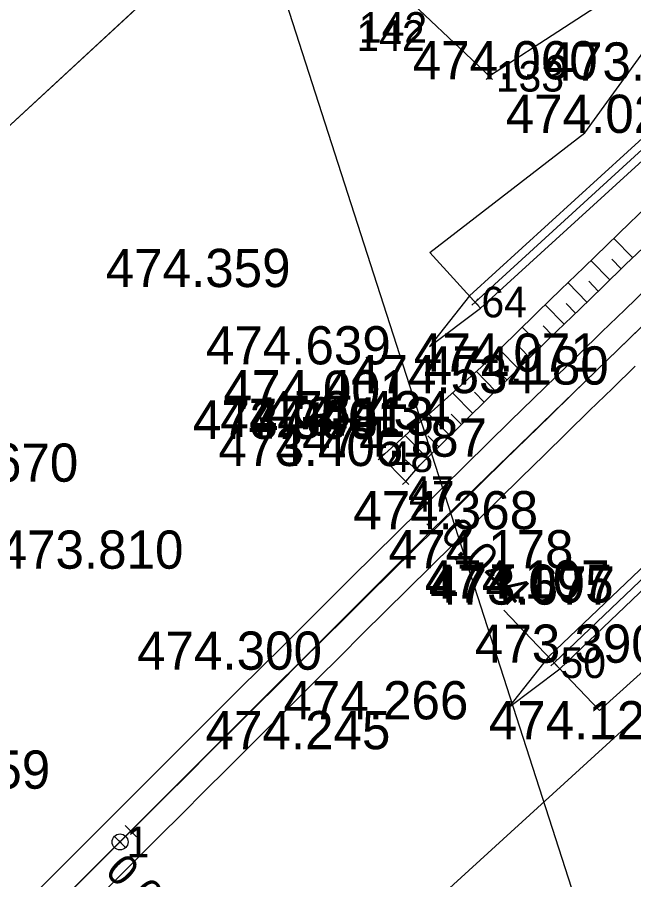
# Model space of a CAD drawing. Extents: x -758836 to -757729, y -1175316 to -1174366.
# Drawn here: x -758436.44 to -758417.1, y -1174871.85 to -1174844.78 of the extents above; entities that cross this region are included whole.
import ezdxf

# ---------------------------------------------------------------- set-up
doc = ezdxf.new("R2010")
doc.units = 0
for name, color, linetype in [('_NOR-body-Nolč', 7, 'Continuous'), ('_NOR-body-stávající osa', 7, 'Continuous'), ('_NOR-návrh tenká', 7, 'Continuous'), ('_NOR-osa', 7, 'Continuous'), ('_NOR-popis', 7, 'Continuous'), ('_NOR-posuny', 7, 'Continuous'), ('_NOR-svahy', 7, 'Continuous'), ('_NOR-vytyčení', 7, 'Continuous'), ('_vytyčený bod', 7, 'Continuous'), ('G_Obvod stavby', 7, 'Continuous'), ('Hranice parcel', 7, 'Continuous'), ('KOS_kabely SSZT', 7, 'Continuous'), ('Vrstva 1', 7, 'Continuous'), ('Vrstva 61', 7, 'Continuous')]:
    doc.layers.add(name, color=color, linetype=linetype)

# ---------------------------------------------------------------- blocks, each defined once
blk = doc.blocks.new('POINT_DISPLAY')
for p, q in [((-0.175, -0.175), (0.175, 0.175)), ((-0.175, 0.175), (0.175, -0.175))]:
    blk.add_line(p, q)

msp = doc.modelspace()

# ---------------------------------------------------------------- linework, layer by layer
at = {"layer": '_NOR-návrh tenká'}
for p, q in [((-758422.251, -1174853.527), (-758412.913, -1174844.999)), ((-758422.076, -1174853.719), (-758412.725, -1174845.179)), ((-758421.9, -1174853.911), (-758412.538, -1174845.36)), ((-758419.775, -1174864.854), (-758406.31, -1174852.017)), ((-758423.492, -1174852.168), (-758421.9, -1174853.911)), ((-758419.596, -1174865.042), (-758406.131, -1174852.205)), ((-758419.417, -1174865.23), (-758405.951, -1174852.393)), ((-758422.251, -1174853.527), (-758423.506, -1174855.117)), ((-758423.506, -1174855.117), (-758421.9, -1174853.911)), ((-758418.166, -1174866.541), (-758408.177, -1174857.467)), ((-758425.015, -1174858.575), (-758424.251, -1174859.35)), ((-758421.172, -1174863.389), (-758418.166, -1174866.541)), ((-758419.775, -1174864.854), (-758421.024, -1174866.442)), ((-758421.024, -1174866.442), (-758419.417, -1174865.23))]:
    msp.add_line(p, q, dxfattribs=at)
for points in [[(-758423.492, -1174852.168), (-758418.628, -1174848.411), (-758415.351, -1174843.865), (-758413.475, -1174842.592)], [(-758425.015, -1174858.575), (-758421.886, -1174855.769), (-758421.539, -1174855.429), (-758420.821, -1174854.729), (-758420.102, -1174854.029), (-758419.383, -1174853.33), (-758418.662, -1174852.631), (-758417.941, -1174851.934), (-758417.218, -1174851.237), (-758416.494, -1174850.542), (-758415.769, -1174849.847), (-758415.043, -1174849.154), (-758414.315, -1174848.461), (-758413.586, -1174847.77), (-758412.856, -1174847.08), (-758412.472, -1174846.718), (-758410.523, -1174846.054)], [(-758424.251, -1174859.35), (-758423.804, -1174858.844), (-758423.09, -1174858.141), (-758422.376, -1174857.439), (-758421.661, -1174856.738), (-758420.944, -1174856.037), (-758420.227, -1174855.337), (-758419.51, -1174854.638), (-758418.791, -1174853.94), (-758418.071, -1174853.242), (-758417.35, -1174852.545), (-758416.628, -1174851.85), (-758415.905, -1174851.155), (-758415.181, -1174850.461), (-758414.456, -1174849.769), (-758413.73, -1174849.077), (-758413.002, -1174848.387), (-758412.273, -1174847.698), (-758411.543, -1174847.01), (-758410.811, -1174846.324), (-758410.523, -1174846.054)], [(-758444.324, -1174880.698), (-758433.744, -1174870.135), (-758433.036, -1174869.428), (-758432.329, -1174868.722), (-758431.621, -1174868.015), (-758430.913, -1174867.309), (-758430.204, -1174866.602), (-758429.496, -1174865.896), (-758428.787, -1174865.19), (-758428.078, -1174864.485), (-758427.369, -1174863.78), (-758426.659, -1174863.075), (-758425.949, -1174862.37), (-758425.238, -1174861.666), (-758424.527, -1174860.962), (-758423.815, -1174860.259), (-758423.102, -1174859.556), (-758422.389, -1174858.854), (-758421.675, -1174858.153), (-758420.961, -1174857.452), (-758420.245, -1174856.752), (-758419.529, -1174856.053), (-758418.812, -1174855.355), (-758418.094, -1174854.657), (-758417.376, -1174853.961), (-758416.656, -1174853.265)], [(-758443.264, -1174881.76), (-758432.684, -1174871.196), (-758431.976, -1174870.49), (-758431.269, -1174869.783), (-758430.561, -1174869.077), (-758429.853, -1174868.371), (-758429.145, -1174867.665), (-758428.437, -1174866.959), (-758427.729, -1174866.254), (-758427.02, -1174865.548), (-758426.311, -1174864.844), (-758425.602, -1174864.139), (-758424.893, -1174863.435), (-758424.183, -1174862.732), (-758423.472, -1174862.029), (-758422.761, -1174861.327), (-758422.049, -1174860.625), (-758421.337, -1174859.924), (-758420.625, -1174859.223), (-758419.911, -1174858.524), (-758419.197, -1174857.825), (-758418.482, -1174857.127), (-758417.766, -1174856.43), (-758417.05, -1174855.734)]]:
    msp.add_lwpolyline(points, dxfattribs=at)
at = {"layer": '_NOR-osa'}
msp.add_line((-758443.794, -1174881.229), (-758433.214, -1174870.666), dxfattribs=at)
msp.add_lwpolyline([(-758433.214, -1174870.666), (-758432.506, -1174869.959), (-758431.799, -1174869.252), (-758431.091, -1174868.546), (-758430.383, -1174867.84), (-758429.675, -1174867.134), (-758428.967, -1174866.428), (-758428.258, -1174865.722), (-758427.549, -1174865.017), (-758426.84, -1174864.312), (-758426.131, -1174863.607), (-758425.421, -1174862.903), (-758424.71, -1174862.199), (-758423.999, -1174861.496), (-758423.288, -1174860.793), (-758422.576, -1174860.091), (-758421.863, -1174859.389), (-758421.15, -1174858.688), (-758420.436, -1174857.988), (-758419.721, -1174857.289), (-758419.006, -1174856.59), (-758418.289, -1174855.892), (-758417.572, -1174855.196), (-758416.854, -1174854.5)], dxfattribs=at)
msp.add_circle((-758433.214, -1174870.666), 0.25, dxfattribs=at)
at = {"layer": '_NOR-popis'}
msp.add_lwpolyline([(-758421.971, -1174894), (-758412.929, -1174891.088), (-758431.963, -1174831.996)], dxfattribs=at)
at = {"layer": '_NOR-svahy'}
for points in [[(-758417.129, -1174852.332), (-758417.719, -1174851.72)], [(-758417.848, -1174853.027), (-758418.439, -1174852.416)], [(-758417.489, -1174852.679), (-758417.784, -1174852.374)], [(-758418.567, -1174853.723), (-758419.158, -1174853.112)], [(-758418.208, -1174853.375), (-758418.504, -1174853.069)], [(-758419.284, -1174854.419), (-758419.877, -1174853.81)], [(-758418.926, -1174854.071), (-758419.222, -1174853.766)], [(-758419.643, -1174854.768), (-758419.939, -1174854.463)], [(-758420.001, -1174855.117), (-758420.594, -1174854.508)], [(-758420.717, -1174855.815), (-758421.311, -1174855.207)], [(-758420.359, -1174855.466), (-758420.656, -1174855.162)], [(-758421.432, -1174856.514), (-758422.032, -1174855.9)], [(-758421.074, -1174856.164), (-758421.372, -1174855.861)], [(-758422.146, -1174857.214), (-758422.778, -1174856.569)], [(-758421.789, -1174856.864), (-758422.097, -1174856.55)], [(-758422.859, -1174857.915), (-758423.524, -1174857.238)], [(-758422.503, -1174857.564), (-758422.827, -1174857.234)], [(-758423.572, -1174858.616), (-758424.27, -1174857.907)], [(-758423.216, -1174858.265), (-758423.557, -1174857.919)], [(-758423.92, -1174858.975), (-758424.308, -1174858.632)]]:
    msp.add_lwpolyline(points, dxfattribs=at)
at = {"layer": '_vytyčený bod'}
for p, q in [((-758421.625, -1174846.633), (-758421.725, -1174846.533)), ((-758421.625, -1174846.633), (-758421.725, -1174846.733)), ((-758421.625, -1174846.633), (-758421.525, -1174846.533)), ((-758421.625, -1174846.633), (-758421.525, -1174846.733)), ((-758422.076, -1174853.719), (-758422.176, -1174853.619)), ((-758422.076, -1174853.719), (-758421.976, -1174853.619)), ((-758422.076, -1174853.719), (-758422.176, -1174853.819)), ((-758422.076, -1174853.719), (-758421.976, -1174853.819)), ((-758425.015, -1174858.575), (-758425.115, -1174858.475)), ((-758425.015, -1174858.575), (-758424.915, -1174858.475)), ((-758425.015, -1174858.575), (-758425.115, -1174858.675)), ((-758425.015, -1174858.575), (-758424.915, -1174858.675)), ((-758424.251, -1174859.35), (-758424.351, -1174859.25)), ((-758424.251, -1174859.35), (-758424.351, -1174859.45)), ((-758424.251, -1174859.35), (-758424.151, -1174859.25)), ((-758424.251, -1174859.35), (-758424.151, -1174859.45)), ((-758419.596, -1174865.042), (-758419.696, -1174864.942)), ((-758419.596, -1174865.042), (-758419.696, -1174865.142)), ((-758419.596, -1174865.042), (-758419.496, -1174864.942)), ((-758419.596, -1174865.042), (-758419.496, -1174865.142)), ((-758433.214, -1174870.665), (-758433.314, -1174870.565)), ((-758433.214, -1174870.665), (-758433.314, -1174870.765)), ((-758433.214, -1174870.665), (-758433.114, -1174870.565)), ((-758433.214, -1174870.665), (-758433.114, -1174870.765))]:
    msp.add_line(p, q, dxfattribs=at)
at = {"layer": 'G_Obvod stavby'}
for points in [[(-758424.368, -1174835.441), (-758423.81, -1174836.28), (-758457.56, -1174867.46)], [(-758457.56, -1174867.46), (-758444.33, -1174881.69), (-758438.77, -1174887.67), (-758435.375, -1174884.045), (-758431.98, -1174880.42), (-758414.84, -1174864.78), (-758400.066, -1174851.383)]]:
    msp.add_lwpolyline(points, dxfattribs=at)
at = {"layer": 'Hranice parcel'}
msp.add_line((-758457.56, -1174867.46), (-758423.81, -1174836.28), dxfattribs=at)
msp.add_lwpolyline([(-758398.4, -1174849.12), (-758399.71, -1174851.06), (-758414.84, -1174864.78), (-758431.98, -1174880.42)], dxfattribs=at)
at = {"layer": 'KOS_kabely SSZT'}
msp.add_lwpolyline([(-758393.377, -1174840.127), (-758394.523, -1174839.636), (-758402.059, -1174830.861), (-758402.489, -1174830.243), (-758402.873, -1174830.574), (-758402.896, -1174831.429), (-758411.837, -1174839.758), (-758412.685, -1174838.202), (-758411.837, -1174839.758), (-758414.56, -1174842.041), (-758415.093, -1174841.478), (-758414.56, -1174842.041), (-758421.625, -1174846.632), (-758424.748, -1174843.672)], dxfattribs=at)
at = {"layer": 'Vrstva 1'}
msp.add_lwpolyline([(-758443.817, -1174881.252), (-758441.673, -1174879.1), (-758423.412, -1174860.854), (-758412.446, -1174850.23), (-758405.322, -1174843.614), (-758399.028, -1174837.996), (-758392.64, -1174832.554), (-758380.106, -1174822.693), (-758371.773, -1174816.721), (-758363.37, -1174811.125), (-758354.46, -1174805.649), (-758345.526, -1174800.592), (-758336.614, -1174795.909), (-758327.338, -1174791.462), (-758317.813, -1174787.314), (-758307.666, -1174783.315), (-758298.059, -1174779.921), (-758285.017, -1174775.914), (-758275.047, -1174773.289)], dxfattribs=at)

# ---------------------------------------------------------------- block references
at = {"layer": '_NOR-body-Nolč'}
msp.add_blockref('POINT_DISPLAY', (-758432.875, -1174870.327), dxfattribs=at)
at = {"layer": '_NOR-body-stávající osa'}
msp.add_blockref('POINT_DISPLAY', (-758423.412, -1174860.854), dxfattribs=at)
at = {"layer": '_NOR-vytyčení'}
msp.add_blockref('POINT_DISPLAY', (-758433.214, -1174870.666), dxfattribs=at)

# ---------------------------------------------------------------- texts
at = {"layer": '_NOR-body-Nolč'}
msp.add_text('0,000  (číslo bodu 66 - projekt p. Nolč)', height=0.95992, rotation=314.9548, dxfattribs=at).set_placement((-758433.723, -1174871.632))
at = {"layer": '_NOR-posuny'}
msp.add_text('0,044', height=0.9599, rotation=314.648, dxfattribs=at).set_placement((-758423.206, -1174861.063))
at = {"layer": '_vytyčený bod'}
for s, height, p in [('142', 0.9599, (-758425.72, -1174845.58)), ('142', 0.9596, (-758425.798, -1174845.835)), ('133', 0.9599, (-758421.425, -1174847.113)), ('133', 0.9596, (-758421.425, -1174847.113)), ('64', 0.9599, (-758421.876, -1174854.199)), ('64', 0.9596, (-758421.876, -1174854.199)), ('48', 0.9599, (-758424.815, -1174859.055)), ('48', 0.9596, (-758424.815, -1174859.055)), ('47', 0.9599, (-758424.174, -1174860.146)), ('47', 0.9596, (-758424.147, -1174860.298)), ('50', 0.9599, (-758419.396, -1174865.522)), ('50', 0.9596, (-758419.396, -1174865.522)), ('1', 0.96, (-758433.014, -1174871.145)), ('1', 0.96, (-758433.014, -1174871.145))]:
    msp.add_text(s, height=height, dxfattribs=at).set_placement(p)
at = {"layer": 'Vrstva 61'}
for s, p in [('474.060', (-758424.03, -1174846.73)), ('473.382', (-758419.863, -1174846.769)), ('474.028', (-758421.113, -1174848.411)), ('474.359', (-758433.664, -1174853.25)), ('474.639', (-758430.52, -1174855.677)), ('474.071', (-758423.995, -1174855.907)), ('474.180', (-758423.681, -1174856.311)), ('474.534', (-758425.966, -1174856.58)), ('474.401', (-758429.96, -1174857.056)), ('474.001', (-758429.973, -1174857.075)), ('473.434', (-758428.648, -1174857.714)), ('473.999', (-758430.931, -1174858.017)), ('474.398', (-758430.925, -1174858.004)), ('474.401', (-758430.069, -1174857.955)), ('474.413', (-758429.164, -1174857.911)), ('473.413', (-758429.162, -1174857.907)), ('474.187', (-758427.5, -1174858.575)), ('473.406', (-758430.127, -1174858.867)), ('474.406', (-758430.126, -1174858.868)), ('474.670', (-758440.325, -1174859.36)), ('474.368', (-758425.897, -1174860.854)), ('473.810', (-758437.025, -1174862.09)), ('474.178', (-758424.789, -1174862.079)), ('474.107', (-758423.653, -1174863.025)), ('474.095', (-758423.529, -1174863.158)), ('473.677', (-758423.484, -1174863.218)), ('473.390', (-758422.081, -1174865.042)), ('474.300', (-758432.679, -1174865.261)), ('474.266', (-758428.086, -1174866.818)), ('474.127', (-758421.645, -1174867.444)), ('474.245', (-758430.532, -1174867.756)), ('473.959', (-758441.205, -1174868.995))]:
    msp.add_text(s, height=1.2, dxfattribs=at).set_placement(p)

doc.saveas('drawing.dxf')
